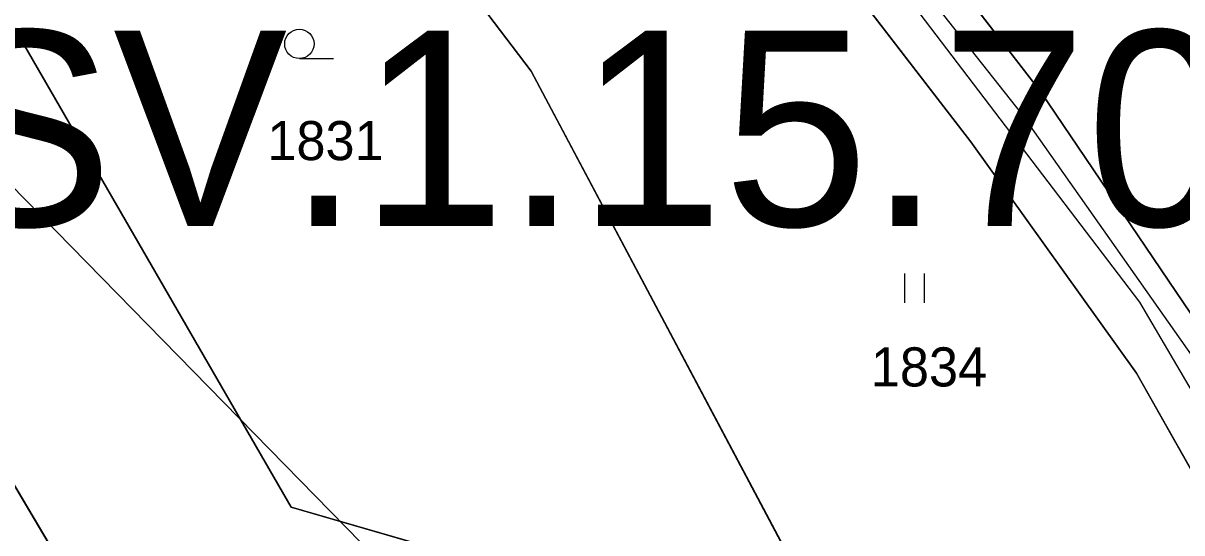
# Model space of a CAD drawing. Extents: x -706130 to -698555, y -971544 to -967260.
# Drawn here: x -703514.5 to -703455.2, y -970570.3 to -970544.2 of the extents above; entities that cross this region are included whole.
import ezdxf

# ---------------------------------------------------------------- set-up
doc = ezdxf.new("R2010")
doc.units = 0
for name, color, linetype in [('Docházková izochrona - VLAK N', 7, 'Continuous'), ('Hranice intravilán', 7, 'Continuous'), ('KN_Hranice_parcel', 7, 'Continuous'), ('KN_Parcelni cisla', 7, 'Continuous'), ('KN_Polygon parcely', 7, 'Continuous'), ('KN_POZEMKY_14_OSTATNI PLOCHA', 7, 'Continuous'), ('KN_POZEMKY_2_ORNA PUDA', 7, 'Continuous'), ('KN_POZEMKY_5_ZAHRADA', 7, 'Continuous'), ('KN_POZEMKY_7_TTP', 7, 'Continuous'), ('KN_VYUZITI_17_ostatni plocha_ostatni komunikace', 7, 'Continuous'), ('KN_Značky kultur', 7, 'Continuous'), ('Komunikace mistni obsluzne - osy S', 7, 'Continuous'), ('Plochy smíšené obytné venkovské S', 7, 'Continuous'), ('Plochy verejnych prostranstvi - komunikace ostatni S', 7, 'Continuous'), ('Plochy zeleně sídelní ostatní S', 7, 'Continuous'), ('Plochy zemědělské všeobecné CELEK S', 7, 'Continuous'), ('Regulační bloky v krajině S', 7, 'Continuous'), ('Regulační bloky zastavěné S', 7, 'Continuous'), ('Regulační kódy zastavěné S', 7, 'Continuous'), ('Trasy turistické N', 7, 'Continuous'), ('Vodovodní řady - rozváděcí S', 7, 'Continuous'), ('VÝŠKOPIS_vrstevnice hlavní', 7, 'Continuous'), ('Zastavene uzemi N', 7, 'Continuous'), ('Zastavene uzemi plochy N', 7, 'Continuous')]:
    doc.layers.add(name, color=color, linetype=linetype)

msp = doc.modelspace()

# ---------------------------------------------------------------- linework, layer by layer
at = {"layer": 'Docházková izochrona - VLAK N'}
msp.add_circle((-704165.451, -969778.767), 800, dxfattribs=at)
at = {"layer": 'Hranice intravilán'}
msp.add_lwpolyline([(-703529.12, -970544), (-703506.01, -970582.94), (-703490.51, -970587.15), (-703465, -970593.5), (-703435.9, -970600.45)], dxfattribs=at)
at = {"layer": 'KN_Hranice_parcel'}
msp.add_line((-703506.01, -970582.94), (-703529.12, -970544), dxfattribs=at)
for points in [[(-703472.27, -970577.26), (-703488.5, -970546.68), (-703513.76, -970513.44)], [(-703435.9, -970600.45), (-703457.52, -970562.14), (-703466.01, -970550.3), (-703473.58, -970540.46), (-703495.19, -970518.75), (-703498.59, -970513.76)], [(-703493.77, -970514.19), (-703470.1, -970537.81), (-703462.43, -970547.72), (-703453.97, -970560.23), (-703443.67, -970577.78)], [(-703472.27, -970577.26), (-703500.79, -970568.99), (-703515.55, -970543.43)]]:
    msp.add_lwpolyline(points, dxfattribs=at)
at = {"layer": 'KN_Polygon parcely'}
for points in [[(-703416.95, -970645.24), (-703428.02, -970606.74), (-703428.84, -970604.59), (-703432.78, -970597.04), (-703442.73, -970579.48), (-703443.67, -970577.78), (-703453.97, -970560.23), (-703462.43, -970547.72), (-703470.1, -970537.81), (-703493.77, -970514.19), (-703497.27, -970509.64), (-703506.19, -970495.76), (-703510.1, -970487.3), (-703515.47, -970480.09), (-703525.04, -970463.09), (-703530.1, -970456.69), (-703539.12, -970446.53), (-703545.12, -970435.39), (-703545.45, -970434.87), (-703561.53, -970421.29), (-703572.42, -970408.81), (-703575.44, -970405.35), (-703593.78, -970387.2)], [(-703596.35, -970390.14), (-703584.57, -970401.94), (-703581.81, -970404.7), (-703561.99, -970426.7), (-703559.69, -970428.44), (-703556.14, -970431.12), (-703548.45, -970436.56), (-703542.22, -970449.4), (-703528.15, -970465.22), (-703518.5, -970481.76), (-703513.69, -970488.66), (-703509.89, -970497.16), (-703501.72, -970509.16), (-703498.59, -970513.76), (-703495.19, -970518.75), (-703473.58, -970540.46), (-703466.01, -970550.3), (-703457.52, -970562.14), (-703435.9, -970600.45), (-703433.43, -970606.34), (-703419.9, -970645.98)]]:
    msp.add_lwpolyline(points, dxfattribs=at)
for points in [[(-703488.5, -970546.68), (-703513.76, -970513.44), (-703532.31, -970511.19), (-703515.55, -970543.43), (-703500.79, -970568.99), (-703472.27, -970577.26)], [(-703473.58, -970540.46), (-703495.19, -970518.75), (-703498.59, -970513.76), (-703513.76, -970513.44), (-703488.5, -970546.68), (-703472.27, -970577.26), (-703465, -970593.5), (-703435.9, -970600.45), (-703457.52, -970562.14), (-703466.01, -970550.3)], [(-703471.7, -970516.59), (-703493.77, -970514.19), (-703470.1, -970537.81), (-703462.43, -970547.72), (-703453.97, -970560.23), (-703443.67, -970577.78), (-703428.94, -970564.62), (-703454.61, -970540.37), (-703449.21, -970529.24), (-703421.16, -970540.34), (-703420.52, -970541.15), (-703414.69, -970541.02), (-703412.23, -970528.86), (-703416, -970528.12), (-703430.69, -970526.61)], [(-703472.27, -970577.26), (-703500.79, -970568.99), (-703515.55, -970543.43), (-703529.12, -970544), (-703506.01, -970582.94), (-703490.51, -970587.15), (-703483.82, -970588.95), (-703465, -970593.5)], [(-703529.12, -970544), (-703606.09, -970547.29), (-703601.48, -970571.41), (-703561.55, -970572.22), (-703534.31, -970579.01), (-703506.01, -970582.94)]]:
    msp.add_lwpolyline(points, close=True, dxfattribs=at)
at = {"layer": 'KN_POZEMKY_14_OSTATNI PLOCHA'}
for p, q in [((-703470.1, -970537.81), (-703462.43, -970547.72)), ((-703466.01, -970550.3), (-703473.58, -970540.46)), ((-703462.43, -970547.72), (-703453.97, -970560.23)), ((-703457.52, -970562.14), (-703466.01, -970550.3)), ((-703435.9, -970600.45), (-703457.52, -970562.14))]:
    msp.add_line(p, q, dxfattribs=at)
at = {"layer": 'KN_POZEMKY_2_ORNA PUDA'}
msp.add_line((-703529.12, -970544), (-703506.01, -970582.94), dxfattribs=at)
at = {"layer": 'KN_POZEMKY_5_ZAHRADA'}
for p, q in [((-703513.76, -970513.44), (-703488.5, -970546.68)), ((-703462.43, -970547.72), (-703470.1, -970537.81)), ((-703515.55, -970543.43), (-703500.79, -970568.99)), ((-703500.79, -970568.99), (-703515.55, -970543.43)), ((-703506.01, -970582.94), (-703529.12, -970544)), ((-703488.5, -970546.68), (-703472.27, -970577.26)), ((-703453.97, -970560.23), (-703462.43, -970547.72)), ((-703500.79, -970568.99), (-703472.27, -970577.26)), ((-703472.27, -970577.26), (-703500.79, -970568.99))]:
    msp.add_line(p, q, dxfattribs=at)
at = {"layer": 'KN_POZEMKY_7_TTP'}
for p, q in [((-703488.5, -970546.68), (-703513.76, -970513.44)), ((-703473.58, -970540.46), (-703466.01, -970550.3)), ((-703472.27, -970577.26), (-703488.5, -970546.68)), ((-703466.01, -970550.3), (-703457.52, -970562.14)), ((-703457.52, -970562.14), (-703435.9, -970600.45))]:
    msp.add_line(p, q, dxfattribs=at)
at = {"layer": 'KN_VYUZITI_17_ostatni plocha_ostatni komunikace'}
for p, q in [((-703470.1, -970537.81), (-703462.43, -970547.72)), ((-703466.01, -970550.3), (-703473.58, -970540.46)), ((-703462.43, -970547.72), (-703453.97, -970560.23)), ((-703457.52, -970562.14), (-703466.01, -970550.3)), ((-703435.9, -970600.45), (-703457.52, -970562.14))]:
    msp.add_line(p, q, dxfattribs=at)
at = {"layer": 'KN_Značky kultur'}
for p, q in [((-703500.363, -970546.04), (-703498.613, -970546.04)), ((-703469.381, -970558.54), (-703469.381, -970557.04)), ((-703468.38, -970558.54), (-703468.38, -970557.04))]:
    msp.add_line(p, q, dxfattribs=at)
msp.add_circle((-703500.363, -970545.29), 0.75, dxfattribs=at)
at = {"layer": 'Komunikace mistni obsluzne - osy S'}
msp.add_lwpolyline([(-703799.428, -970313.344), (-703772.67, -970319.119), (-703743.027, -970323.757), (-703708.137, -970333.12), (-703680.068, -970339.508), (-703649.725, -970350.621), (-703637.833, -970358.584), (-703617.917, -970371.863), (-703601.041, -970383.676), (-703594.395, -970389.101), (-703577.781, -970405.465), (-703560.38, -970424.891), (-703546.214, -970436.092), (-703539.83, -970448.867), (-703526.801, -970463.743), (-703512.023, -970487.895), (-703508.088, -970496.558), (-703493.66, -970517.034), (-703472.761, -970538.298), (-703457.371, -970558.511), (-703445.042, -970579.512), (-703433.936, -970599.551), (-703430.788, -970606.026), (-703418.218, -970645.464)], dxfattribs=at)
at = {"layer": 'Plochy smíšené obytné venkovské S'}
for p, q in [((-703470.1, -970537.81), (-703462.43, -970547.72)), ((-703529.12, -970544), (-703506.01, -970582.94))]:
    msp.add_line(p, q, dxfattribs=at)
for points in [[(-703472.27, -970577.26), (-703488.5, -970546.68), (-703513.76, -970513.44)], [(-703462.43, -970547.72), (-703453.97, -970560.23), (-703443.67, -970577.78)]]:
    msp.add_lwpolyline(points, dxfattribs=at)
at = {"layer": 'Plochy verejnych prostranstvi - komunikace ostatni S'}
for points in [[(-703636.11, -970363.08), (-703623.01, -970370.91), (-703622.48, -970371.21), (-703611.55, -970379.16), (-703596.35, -970390.14), (-703584.57, -970401.94), (-703581.81, -970404.7), (-703561.99, -970426.7), (-703559.69, -970428.44), (-703556.14, -970431.12), (-703548.45, -970436.56), (-703542.22, -970449.4), (-703528.15, -970465.22), (-703518.5, -970481.76), (-703513.69, -970488.66), (-703509.89, -970497.16), (-703501.72, -970509.16), (-703498.59, -970513.76), (-703495.19, -970518.75), (-703473.58, -970540.46), (-703466.01, -970550.3), (-703457.52, -970562.14), (-703435.9, -970600.45)], [(-703416.95, -970645.24), (-703428.02, -970606.74), (-703428.84, -970604.59), (-703432.78, -970597.04), (-703442.73, -970579.48), (-703443.67, -970577.78), (-703453.97, -970560.23), (-703462.43, -970547.72), (-703470.1, -970537.81), (-703493.77, -970514.19), (-703497.27, -970509.64), (-703506.19, -970495.76), (-703510.1, -970487.3), (-703515.47, -970480.09), (-703525.04, -970463.09), (-703530.1, -970456.69), (-703539.12, -970446.53), (-703545.12, -970435.39), (-703545.45, -970434.87), (-703561.53, -970421.29), (-703572.42, -970408.81), (-703575.44, -970405.35), (-703593.78, -970387.2)]]:
    msp.add_lwpolyline(points, dxfattribs=at)
at = {"layer": 'Plochy zeleně sídelní ostatní S'}
for p, q in [((-703513.76, -970513.44), (-703488.5, -970546.68)), ((-703457.52, -970562.14), (-703466.01, -970550.3)), ((-703435.9, -970600.45), (-703457.52, -970562.14))]:
    msp.add_line(p, q, dxfattribs=at)
for points in [[(-703466.01, -970550.3), (-703473.58, -970540.46), (-703495.19, -970518.75), (-703498.59, -970513.76)], [(-703488.5, -970546.68), (-703472.27, -970577.26), (-703465, -970593.5)]]:
    msp.add_lwpolyline(points, dxfattribs=at)
at = {"layer": 'Plochy zemědělské všeobecné CELEK S'}
msp.add_line((-703506.01, -970582.94), (-703529.12, -970544), dxfattribs=at)
at = {"layer": 'Regulační bloky v krajině S'}
for p, q in [((-703513.76, -970513.44), (-703488.5, -970546.68)), ((-703466.01, -970550.3), (-703473.58, -970540.46)), ((-703506.01, -970582.94), (-703529.12, -970544)), ((-703457.52, -970562.14), (-703466.01, -970550.3)), ((-703435.9, -970600.45), (-703457.52, -970562.14))]:
    msp.add_line(p, q, dxfattribs=at)
msp.add_lwpolyline([(-703488.5, -970546.68), (-703472.27, -970577.26), (-703465, -970593.5)], dxfattribs=at)
at = {"layer": 'Regulační bloky zastavěné S'}
for p, q in [((-703470.1, -970537.81), (-703462.43, -970547.72)), ((-703529.12, -970544), (-703506.01, -970582.94))]:
    msp.add_line(p, q, dxfattribs=at)
for points in [[(-703636.11, -970363.08), (-703623.01, -970370.91), (-703622.48, -970371.21), (-703611.55, -970379.16), (-703596.35, -970390.14), (-703584.57, -970401.94), (-703581.81, -970404.7), (-703561.99, -970426.7), (-703559.69, -970428.44), (-703556.14, -970431.12), (-703548.45, -970436.56), (-703542.22, -970449.4), (-703528.15, -970465.22), (-703518.5, -970481.76), (-703513.69, -970488.66), (-703509.89, -970497.16), (-703501.72, -970509.16), (-703498.59, -970513.76), (-703495.19, -970518.75), (-703473.58, -970540.46), (-703466.01, -970550.3), (-703457.52, -970562.14), (-703435.9, -970600.45)], [(-703432.78, -970597.04), (-703442.73, -970579.48), (-703443.67, -970577.78), (-703453.97, -970560.23), (-703462.43, -970547.72), (-703470.1, -970537.81), (-703493.77, -970514.19), (-703497.27, -970509.64), (-703506.19, -970495.76), (-703510.1, -970487.3), (-703515.47, -970480.09), (-703525.04, -970463.09), (-703530.1, -970456.69), (-703539.12, -970446.53), (-703545.12, -970435.39), (-703545.45, -970434.87), (-703561.53, -970421.29), (-703572.42, -970408.81), (-703575.44, -970405.35), (-703593.78, -970387.2)], [(-703472.27, -970577.26), (-703488.5, -970546.68), (-703513.76, -970513.44)], [(-703462.43, -970547.72), (-703453.97, -970560.23), (-703443.67, -970577.78)]]:
    msp.add_lwpolyline(points, dxfattribs=at)
at = {"layer": 'Trasy turistické N'}
msp.add_lwpolyline([(-703639.36, -970354.95), (-703605.17, -970378.02), (-703599.73, -970382.19), (-703593.78, -970387.2), (-703575.44, -970405.35), (-703561.53, -970421.29), (-703545.45, -970434.87), (-703539.12, -970446.53), (-703530.1, -970456.69), (-703525.04, -970463.09), (-703515.47, -970480.09), (-703510.1, -970487.3), (-703506.19, -970495.76), (-703497.27, -970509.64), (-703493.77, -970514.19), (-703470.1, -970537.81), (-703462.43, -970547.72), (-703453.97, -970560.23), (-703443.67, -970577.78), (-703432.78, -970597.04), (-703428.84, -970604.59), (-703428.02, -970606.74), (-703416.95, -970645.24)], dxfattribs=at)
at = {"layer": 'Vodovodní řady - rozváděcí S'}
msp.add_lwpolyline([(-703414.392, -970657.693), (-703429.867, -970607.822), (-703442.266, -970580.55), (-703453.418, -970563.041), (-703463.4, -970548.877), (-703475.5, -970533.543), (-703488.102, -970519.658), (-703499.868, -970504.849), (-703513.523, -970483.871), (-703531.459, -970457.7), (-703535.385, -970452.279), (-703550.662, -970437.263), (-703601.286, -970390.979), (-703638.654, -970361.134), (-703658.242, -970351.978), (-703680.412, -970345.708), (-703705.115, -970338.641), (-703778.014, -970321.904)], dxfattribs=at)
at = {"layer": 'VÝŠKOPIS_vrstevnice hlavní'}
msp.add_lwpolyline([(-703454.843, -970623.488), (-703465.543, -970607.509), (-703471.678, -970599.52), (-703495.647, -970572.412), (-703522.184, -970545.304), (-703540.731, -970528.755), (-703567.125, -970508.781), (-703583.104, -970498.223), (-703603.078, -970488.093), (-703623.338, -970480.96), (-703637.89, -970479.105), (-703650.73, -970478.82), (-703666.139, -970482.957), (-703682.545, -970490.804), (-703700.094, -970501.362), (-703706.942, -970503.93), (-703714.361, -970505.642), (-703723.778, -970505.785), (-703733.765, -970504.358), (-703759.731, -970496.511), (-703772, -970494.514), (-703792.545, -970495.084)], dxfattribs=at)
at = {"layer": 'Zastavene uzemi N'}
msp.add_lwpolyline([(-703671.68, -970421.04), (-703635.34, -970415.7), (-703634.18, -970419.42), (-703597.37, -970419.27), (-703581.81, -970404.7), (-703561.99, -970426.7), (-703559.69, -970428.44), (-703556.14, -970431.12), (-703548.45, -970436.56), (-703542.22, -970449.4), (-703528.15, -970465.22), (-703518.5, -970481.76), (-703513.69, -970488.66), (-703509.89, -970497.16), (-703501.72, -970509.16), (-703498.59, -970513.76), (-703513.76, -970513.44), (-703532.31, -970511.19), (-703537.56, -970510.55), (-703529.12, -970544), (-703506.01, -970582.94), (-703496.74, -970590.39), (-703433.43, -970606.34), (-703419.9, -970645.98)], dxfattribs=at)
at = {"layer": 'Zastavene uzemi plochy N'}
msp.add_lwpolyline([(-703671.68, -970421.04), (-703635.34, -970415.7), (-703634.18, -970419.42), (-703597.37, -970419.27), (-703581.81, -970404.7), (-703561.99, -970426.7), (-703559.69, -970428.44), (-703556.14, -970431.12), (-703548.45, -970436.56), (-703542.22, -970449.4), (-703528.15, -970465.22), (-703518.5, -970481.76), (-703513.69, -970488.66), (-703509.89, -970497.16), (-703501.72, -970509.16), (-703498.59, -970513.76), (-703513.76, -970513.44), (-703532.31, -970511.19), (-703537.56, -970510.55), (-703529.12, -970544), (-703506.01, -970582.94), (-703496.74, -970590.39), (-703433.43, -970606.34), (-703419.9, -970645.98)], dxfattribs=at)

# ---------------------------------------------------------------- texts
at = {"layer": 'KN_Parcelni cisla'}
for s, p in [('1831', (-703502, -970551.24)), ('1834', (-703471.12, -970562.82))]:
    msp.add_text(s, height=2, dxfattribs=at).set_placement(p)
at = {"layer": 'Regulační kódy zastavěné S'}
msp.add_text('SV.1.15.70', height=10, dxfattribs=at).set_placement((-703518.813, -970554.611))

doc.saveas('drawing.dxf')
